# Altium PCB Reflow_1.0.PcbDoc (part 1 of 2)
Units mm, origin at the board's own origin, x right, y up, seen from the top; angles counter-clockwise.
Board outline 183 x 128.5 mm, 2 copper layers (Top Layer, Bottom Layer); 137 components, 94 nets, 418 pads, 91 vias.
Unrouted connection lines stored in the file: 2.
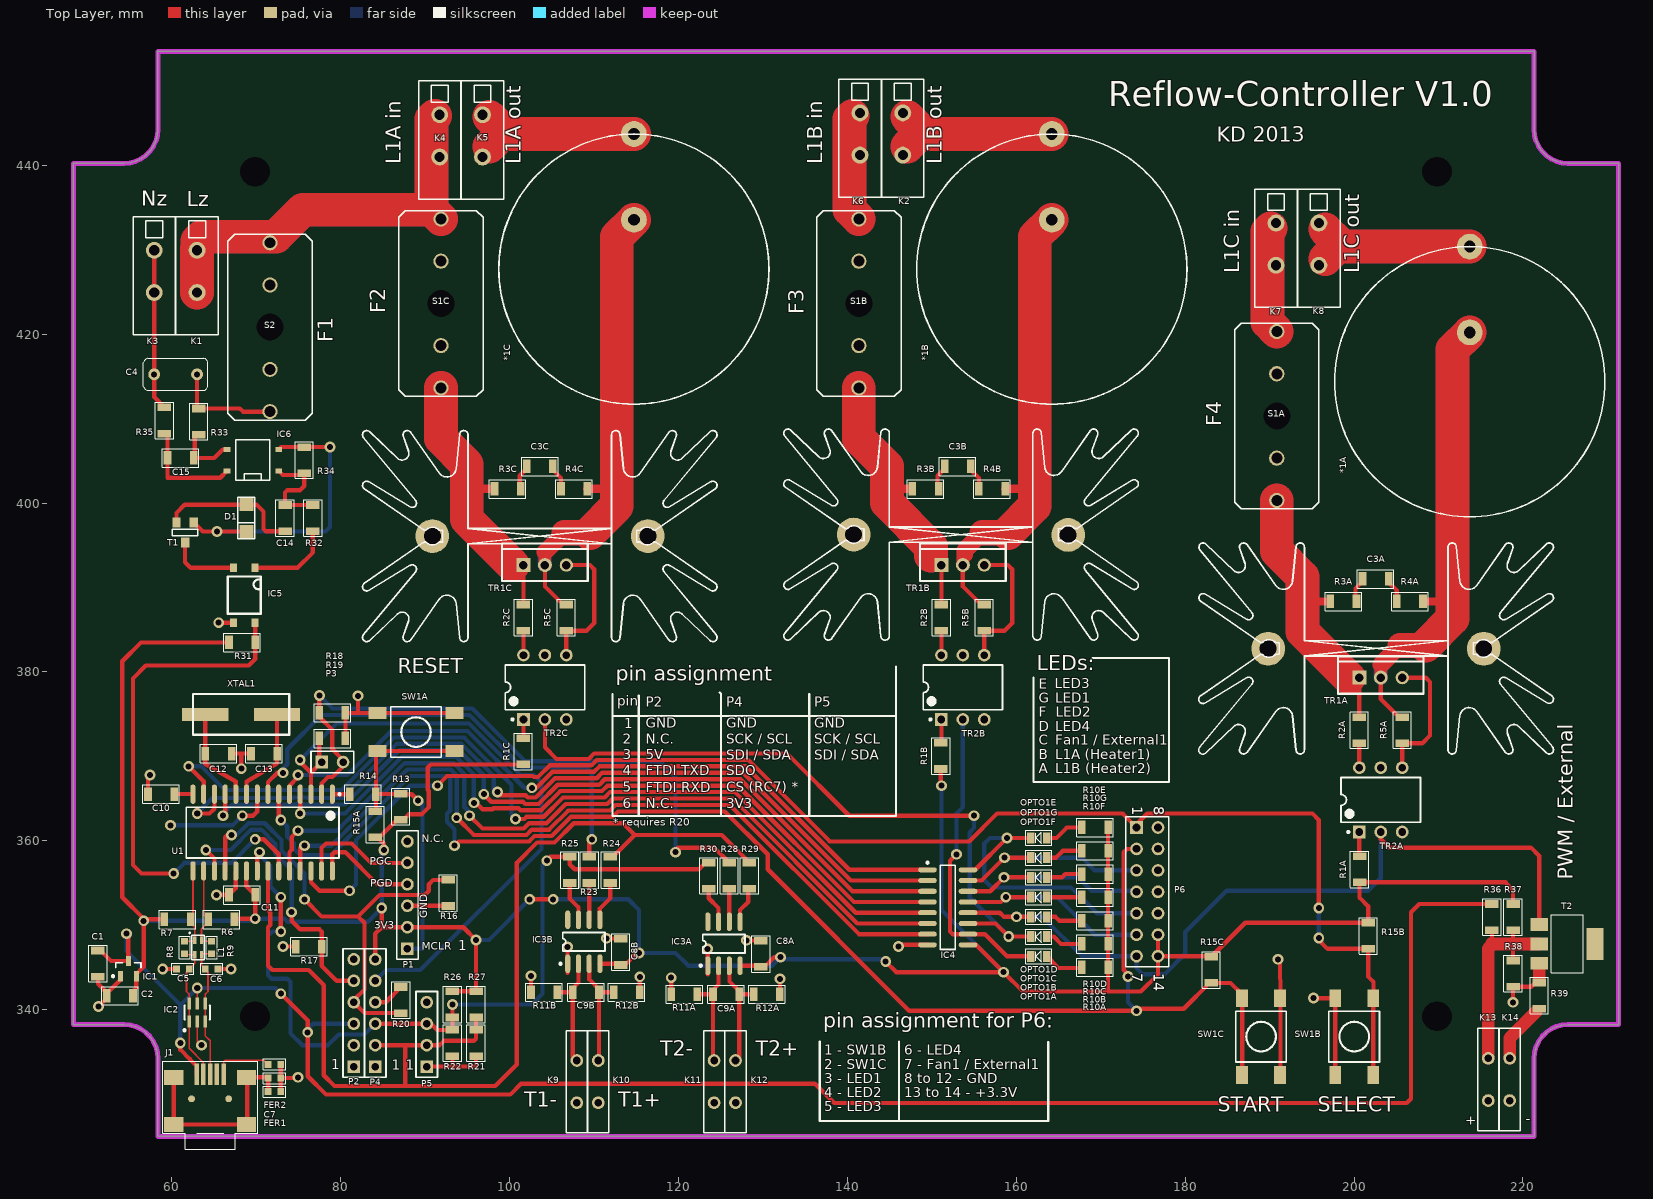
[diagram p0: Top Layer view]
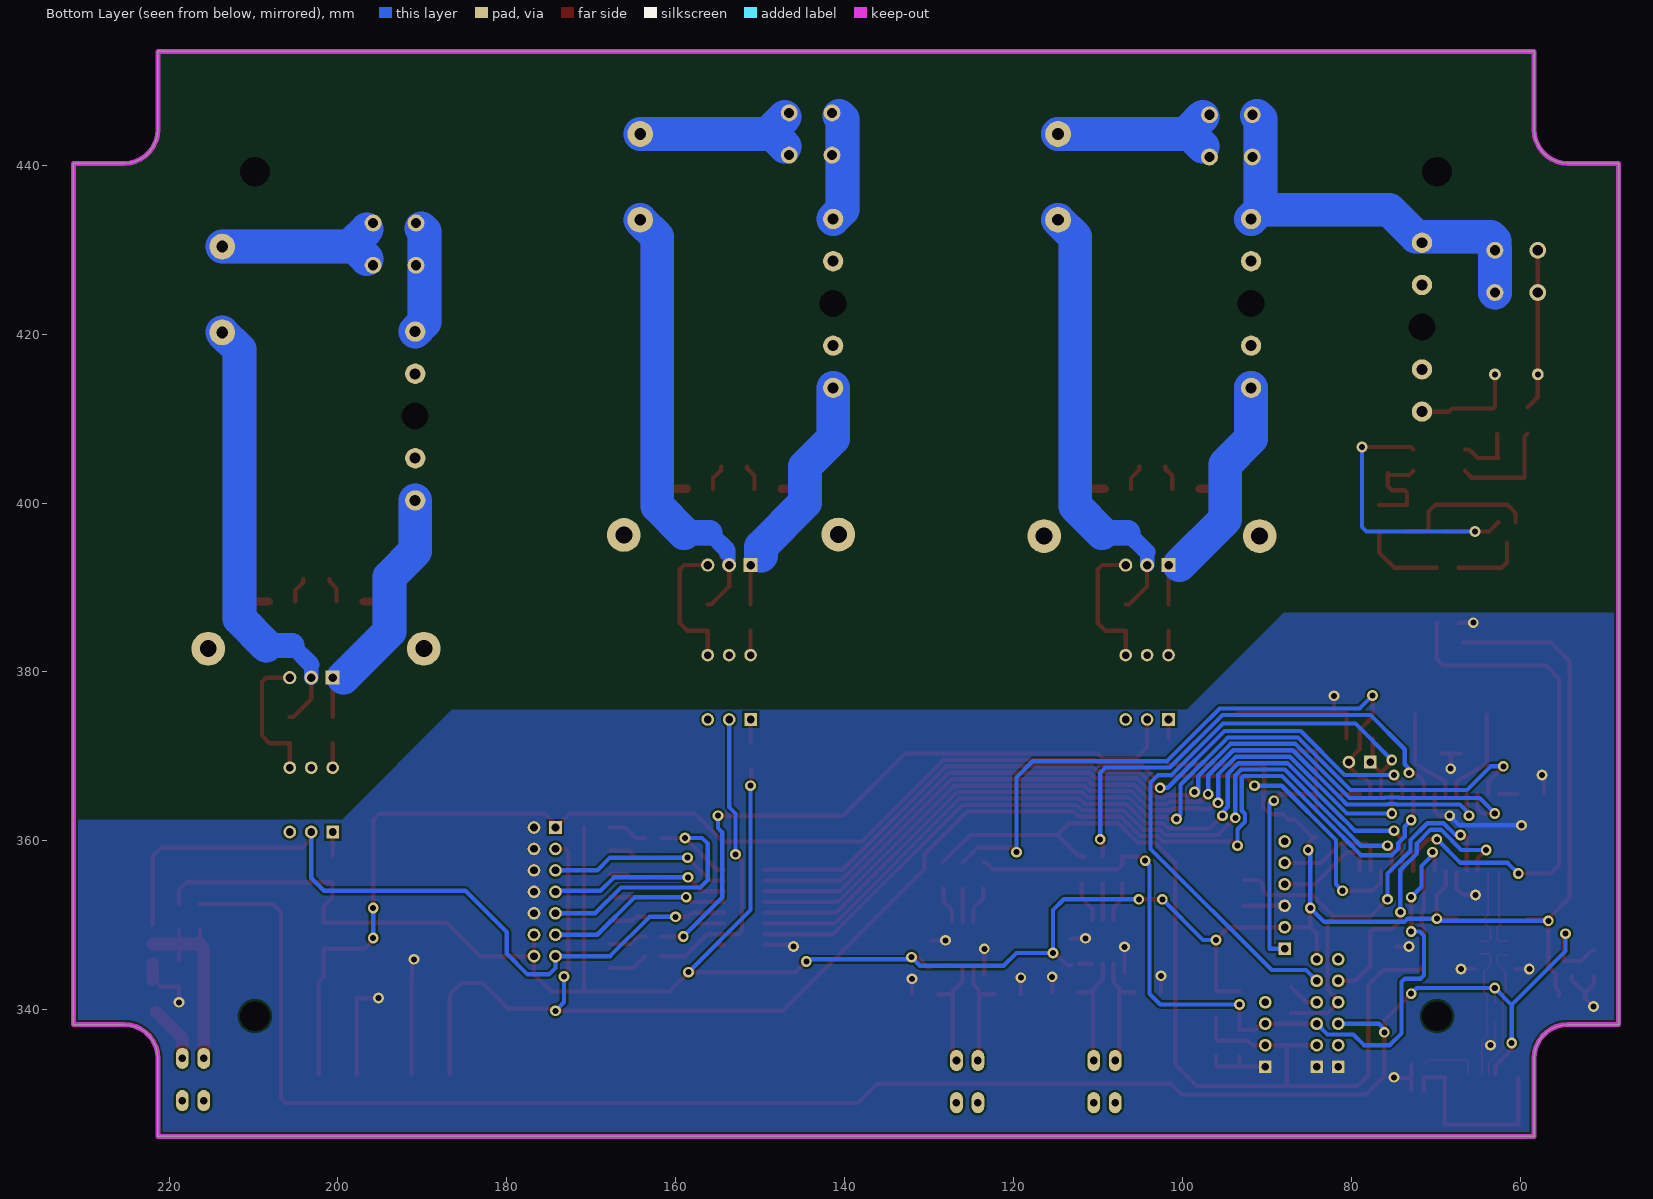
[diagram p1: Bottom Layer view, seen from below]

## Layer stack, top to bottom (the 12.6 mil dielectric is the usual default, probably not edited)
Top Layer: signal copper 0.0356
Dielectric: dielectric 0.32, FR-4, Dk 4.8
Bottom Layer: signal copper 0.0356

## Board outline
48.331,338.232 54.331,338.232 55.026,338.171 55.699,337.991 56.331,337.696 56.902,337.296 57.395,336.803 57.795,336.232 58.09,335.6 58.27,334.927 58.331,334.232 58.331,324.982 221.331,324.982 221.331,334.232 221.392,334.927 221.572,335.6 221.867,336.232 222.267,336.803 222.76,337.296 223.331,337.696 223.963,337.991 224.636,338.171 225.331,338.232 231.331,338.232 231.331,440.232 225.331,440.232 224.636,440.293 223.963,440.473 223.331,440.768 222.76,441.168 222.267,441.661 221.867,442.232 221.572,442.864 221.392,443.537 221.331,444.232 221.331,453.482 58.331,453.482 58.331,444.232 58.27,443.537 58.09,442.864 57.795,442.232 57.395,441.661 56.902,441.168 56.331,440.768 55.699,440.473 55.026,440.293 54.331,440.232 48.331,440.232

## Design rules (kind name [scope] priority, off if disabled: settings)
Clearance [All] p1: gap=0.254
ComponentClearance [All] p1 off: gap=0.254 collisioncheckmode=3 verticalgap=0.254 showdistances=FALSE
DiffPairsRouting [All] p1 off: maxlimit=0.254 minlimit=0.254 mostfreqgap=0.254 maxuncoupledlength=12.7
FabricationTestPointUsage [All] p1 off: valid=0 allowmultiple=FALSE
FabricationTestpoint [(IsPad And (OnTopLayer Or OnBottomLayer))] p1 off: side=3 testpointundercomponent=TRUE minsize=1.016 maxsize=2.54 preferedsize=1.524 minholesize=0 maxholesize=1.016 preferedholesize=0.813 testpointgrid=0.025 allowsidetop=TRUE allowsidebottom=TRUE usegrid=TRUE gridtolerance=0
FanoutControl Fanout_BGA [IsBGA] p1 off: bgadir=Out bgaviamode=Centered fanoutstyle=Auto fanoutdirection=Alternating viagrid=0.025 // Fanout_BGA (Default Rule)
FanoutControl Fanout_LCC [IsLCC] p2 off: bgadir=Out bgaviamode=Centered fanoutstyle=Auto fanoutdirection=Alternating viagrid=0.025 // Fanout_LCC (Default Rule)
FanoutControl Fanout_SOIC [IsSOIC] p3 off: bgadir=Out bgaviamode=Centered fanoutstyle=Auto fanoutdirection=Alternating viagrid=0.025 // Fanout_SOIC (Default Rule)
FanoutControl Fanout_Small [(CompPinCount < 5)] p4 off: bgadir=Out bgaviamode=Centered fanoutstyle=Auto fanoutdirection=OutThenIn viagrid=0.025 // Fanout_Small (Default Rule)
FanoutControl Fanout_Default [All] p5 off: bgadir=Out bgaviamode=Centered fanoutstyle=Auto fanoutdirection=Alternating viagrid=0.025 // Fanout_Default (Default Rule)
Height [All] p1 off: minheight=0 maxheight=25.4 prefheight=12.7
HoleSize [All] p1 off: absolutevalues=TRUE maxlimit=2.54 minlimit=0.025 maxpercent=80.000 minpercent=20.000
HoleToHoleClearance [All] p1 off: gap=0.254 allowstackedmicrovias=TRUE
LayerPairs [All] p1 off: enforce=TRUE
MinimumSolderMaskSliver [All] p1 off: minsoldermaskwidth=0.254
NetAntennae [All] p1 off: netantennaetolerance=0
PasteMaskExpansion [All] p1 off: expansion=0
PlaneClearance [All] p1 off: clearance=0.508
PlaneConnect [All] p1 off: planeconnectstyle=Relief reliefexpansion=0.508 reliefentries=4 reliefconductorwidth=0.254 reliefairgap=0.254
PolygonConnect [All] p1 off: connectstyle=Relief reliefconductorwidth=0.254 reliefentries=4 polygonreliefangle="90 Angle" airgapwidth=0.254
RoomDefinition U_SW3 [InComponentClass('U_SW3')] p1 off: confinementstyle=ConfineIn formatcopy=TRUE lockcomponents=FALSE outline 181.356,330.708 193.548,330.708 193.548,347.98 181.356,347.98
RoomDefinition U_SW2 [InComponentClass('U_SW2')] p2 off: confinementstyle=ConfineIn formatcopy=TRUE lockcomponents=FALSE outline 195.072,330.708 206.502,330.708 206.502,348.234 195.072,348.234
RoomDefinition U_SW1 [InComponentClass('U_SW1')] p3 off: confinementstyle=ConfineIn formatcopy=TRUE lockcomponents=FALSE outline 81.026,376.936 81.026,359.41 95.25,359.41 95.25,376.936
RoomDefinition U_AC_SWITCH3 [InComponentClass('U_AC_SWITCH3')] p4 off: confinementstyle=ConfineIn formatcopy=TRUE lockcomponents=FALSE outline 82.069,367.346 131.569,367.346 131.569,452.74 82.069,452.74
RoomDefinition U_AC_SWITCH2 [InComponentClass('U_AC_SWITCH2')] p5 off: confinementstyle=ConfineIn formatcopy=TRUE lockcomponents=FALSE outline 131.569,367.346 181.069,367.346 181.069,452.74 131.569,452.74
RoomDefinition U_ZEROCROSS [InComponentClass('U_ZEROCROSS')] p6 off: confinementstyle=ConfineIn formatcopy=TRUE lockcomponents=FALSE outline 81,380.694 81,436.786 52.813,436.786 52.813,380.694
RoomDefinition "U_USB ESD EMV BUCHSE" [InComponentClass('U_USB ESD EMV BUCHSE')] p7 off: confinementstyle=ConfineIn formatcopy=TRUE lockcomponents=FALSE outline 57.15,323.088 76.2,323.088 76.2,352.298 57.15,352.298
RoomDefinition U_UNL2003_LED [InComponentClass('U_UNL2003_LED')] p8 off: confinementstyle=ConfineIn formatcopy=TRUE lockcomponents=FALSE outline 146.4,325.628 178.816,325.628 178.816,364.744 146.4,364.744
RoomDefinition U_PIC18F2550 [InComponentClass('U_PIC18F2550')] p9 off: confinementstyle=ConfineIn formatcopy=TRUE lockcomponents=FALSE outline 56.134,378.968 56.134,344.678 96.273,344.678 96.273,378.968
RoomDefinition "U_MOSFET OUT" [InComponentClass('U_MOSFET OUT')] p10 off: confinementstyle=ConfineIn formatcopy=TRUE lockcomponents=FALSE outline 213.868,324.612 231.14,324.612 231.14,353.822 213.868,353.822
RoomDefinition U_MAX66752 [InComponentClass('U_MAX66752')] p11 off: confinementstyle=ConfineIn formatcopy=TRUE lockcomponents=FALSE outline 117.856,325.12 117.856,359.083 101.256,359.083 101.256,325.12
RoomDefinition U_MAX66751 [InComponentClass('U_MAX66751')] p12: confinementstyle=ConfineIn formatcopy=TRUE lockcomponents=FALSE outline 134.456,325.12 134.456,358.648 117.856,358.648 117.856,325.12
RoomDefinition U_AC_SWITCH1 [InComponentClass('U_AC_SWITCH1')] p13 off: confinementstyle=ConfineIn formatcopy=TRUE lockcomponents=FALSE outline 181.069,354.013 230.569,354.013 230.569,439.407 181.069,439.407
RoomDefinition U_3V3_Regler [InComponentClass('U_3V3_Regler')] p14 off: confinementstyle=ConfineIn formatcopy=TRUE lockcomponents=FALSE outline 48.26,338.074 57.53,338.074 57.53,349.504 48.26,349.504
RoutingCorners [All] p1 off: cornerstyle=45-Degree minsetback=2.54 maxsetback=2.54
RoutingLayers [All] p1 off: top layer_v5=TRUE bottom layer_v5=TRUE
RoutingPriority [All] p1 off: routingpriority=0
RoutingTopology [All] p1 off: topology=Shortest
RoutingVias [All] p1 off: holewidth=0.711 width=1.27 viastyle="Through Hole" minholewidth=0.711 minwidth=1.27 maxholewidth=0.711 maxwidth=1.27
ShortCircuit [All] p1 off: allowed=FALSE
SilkToSilkClearance [All] p1 off: silktosilkclearance=0.254
SilkscreenOverComponentPads [All] p1 off: minsilkscreentomaskgap=0.254
SolderMaskExpansion [All] p1 off: expansion=0.102
UnRoutedNet [All] p1 off:
Width [All] p1 off: maxlimit=0.254 minlimit=0.254 preferedwidth=0.254
2 further rules are at their usual default settings.

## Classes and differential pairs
channel class SW: U_SW1 U_SW2 U_SW3
channel class MAX6675: U_MAX66751 U_MAX66752
channel class LED: U_LED1 U_LED2 U_LED3 U_LED4 U_LED5 U_LED6 U_LED7
channel class AC_SWITCH: U_AC_SWITCH1 U_AC_SWITCH2 U_AC_SWITCH3
net class OUT[1..7]: OUT1 OUT2 OUT3 OUT4 OUT5 OUT6 OUT7
component class U_ZEROCROSS: C4 C14 C15 D1 IC5 IC6 R31 R32 R33 R34 R35 T1
component class "U_USB ESD EMV BUCHSE": C5 C6 C7 FER1 FER2 IC2 J1 L1 R6 R7 R8 R9
component class U_UNL2003_LED: IC4
component class U_SW3: R15C SW1C
component class U_SW2: R15B SW1B
component class U_SW1: R15A SW1A
component class U_PIC18F2550: C10 C11 C12 C13 P1 R13 R14 U1 XTAL1
component class "U_MOSFET OUT": K13 K14 R36 R37 R38 R39 T2
component class U_MAX66752: C8B C9B IC3B R11B R12B
component class U_MAX66751: C8A C9A IC3A R11A R12A
component class U_LED7: OPTO1G R10G
component class U_LED6: OPTO1F R10F
component class U_LED5: OPTO1E R10E
component class U_LED4: OPTO1D R10D
component class U_LED3: OPTO1C R10C
component class U_LED2: OPTO1B R10B
component class U_LED1: OPTO1A R10A
component class U_AC_SWITCH3: *1C C3C R1C R2C R3C R4C R5C S1C TR1C TR2C
component class U_AC_SWITCH2: *1B C3B R1B R2B R3B R4B R5B S1B TR1B TR2B
component class U_AC_SWITCH1: *1A C3A R1A R2A R3A R4A R5A S1A TR1A TR2A
component class U_3V3_Regler: C1 C2 IC1
component class TOP_Sheet: K1 K2 K3 K4 K5 K6 K7 K8 K9 K10 K11 K12 P2 P3 P4 P5 P6 R16 R17 R18 R19 R20 R21 R22 R23 R24 R25 R26 R27 R28 R29 R30 S2
differential pair USB: +USB_P -USB_N
differential pair USB1: +USB1_P -USB1_N

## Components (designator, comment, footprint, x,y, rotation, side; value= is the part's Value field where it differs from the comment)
*1A "Ringkern-Drossel_1mH_16A_250VAC" "PCBCOMPONENT_1 - DUPLICATE" 213.711,420.213 r90 top (schematic designator *1)
*1B "Ringkern-Drossel_1mH_16A_250VAC" "PCBCOMPONENT_1 - DUPLICATE" 164.211,433.546 r90 top (schematic designator *1)
*1C "Ringkern-Drossel_1mH_16A_250VAC" "PCBCOMPONENT_1 - DUPLICATE" 114.711,433.546 r90 top (schematic designator *1)
C1 "1uF" RLCDT_1206 51.23,345.452 r270 top
C2 "1uF" RLCDT_1206 53.83,341.652 r180 top
C3A "10nF" RLCDT_1206 202.561,391.003 r0 top (schematic designator C3)
C3B "10nF" RLCDT_1206 153.061,404.336 r0 top (schematic designator C3)
C3C "10nF" RLCDT_1206 103.561,404.336 r0 top (schematic designator C3)
C4 "VARISTOR_RM5" C02S200E0E28 62.973,415.238 r180 top
C5 "10pF" RLCDT_0603 61.292,344.816 r0 top
C6 "10pF" RLCDT_0603 64.692,344.816 r180 top
C7 "10nF" RLCDT_0603 72.136,331.895 r0 top
C8A "100nF" RLCDT_1206 129.756,346.601 r90 top (schematic designator C8)
C8B "100nF" RLCDT_1206 113.156,346.836 r90 top (schematic designator C8)
C9A "100nF" RLCDT_1206 125.63,341.83 r180 top (schematic designator C9)
C9B "100nF" RLCDT_1206 109.03,342.065 r180 top (schematic designator C9)
C10 "220nF" RLCDT_1206 58.706,365.528 r180 top
C11 "100nF" RLCDT_1206 68.298,353.586 r180 top
C12 "22pF" RLCDT_1206 65.506,370.328 r180 top
C13 "22pF" RLCDT_1206 70.906,370.328 r0 top
C14 "10uF" RLCDT_1206 73.387,398.22 r270 top
C15 "1nF" RLCDT_1206 61.016,405.332 r180 top
D1 "D_LL4148/MMELF" D02X125Y0A0 68.815,398.22 r90 top
FER1 "742792651" RLCDT_0603 72.136,330.295 r180 top
FER2 "742792651" RLCDT_0603 72.136,333.502 r0 top
IC1 "VRG_XC6206P332MR/SOT23" RLCDT_SOT23 54.83,344.852 r90 top
IC2 "IP4220CZ6" ESD_SOT457 62.992,339.654 r0 top
IC3A "IC_MAX6675" IC_SOIC150_8 125.376,347.799 r0 top (schematic designator IC3)
IC3B "IC_MAX6675" IC_SOIC150_8 108.776,348.034 r0 top (schematic designator IC3)
IC4 "ULN2003L" L16_N 151.88,352.11 r0 top
IC5 "OK_PC357/MFP4" MFP4 68.561,389.076 r180 top
IC6 "GLEICHRICHTER_S80" DO-269AA 69.577,405.078 r90 top
J1 "USB-MINI-B%C" USB-MINI-B_2 66.117,332.338 r180 top
K1 "WAGO-236" KL02X196Y0A0 62.973,427.43 r270 top
K2 "WAGO-236" KL02X196Y0A0 146.565,443.706 r270 top
K3 "WAGO-236" KL02X196Y0A0 57.893,427.43 r270 top
K4 "WAGO-236" KL02X196Y0A0 91.701,443.484 r270 top
K5 "WAGO-236" KL02X196Y0A0 96.781,443.484 r270 top
K6 "WAGO-236" KL02X196Y0A0 141.485,443.706 r270 top
K7 "WAGO-236" KL02X196Y0A0 190.761,430.659 r270 top
K8 "WAGO-236" KL02X196Y0A0 195.841,430.659 r270 top
K9 "WAGO-233" KL02X0Y197A0 107.95,331.47 r180 top
K10 "WAGO-233" KL02X0Y197A0 110.49,331.47 r180 top
K11 "WAGO-233" KL02X0Y197A0 124.206,331.47 r180 top
K12 "WAGO-233" KL02X0Y197A0 126.746,331.47 r180 top
K13 "WAGO-233" KL02X0Y197A0 215.9,331.724 r180 top
K14 "WAGO-233" KL02X0Y197A0 218.44,331.724 r180 top
L1 "744231371" RLCDT_CMC_WÜRTH_CNSW_0805 63.092,347.354 r270 top
OPTO1A "Value" OPTO_0805_POL 162.664,346.31 r180 top (schematic designator OPTO1)
OPTO1B "Value" OPTO_0805_POL 162.664,348.647 r180 top (schematic designator OPTO1)
OPTO1C "Value" OPTO_0805_POL 162.664,350.985 r180 top (schematic designator OPTO1)
OPTO1D "Value" OPTO_0805_POL 162.664,353.322 r180 top (schematic designator OPTO1)
OPTO1E "Value" OPTO_0805_POL 162.664,360.334 r180 top (schematic designator OPTO1)
OPTO1F "Value" OPTO_0805_POL 162.664,355.659 r180 top (schematic designator OPTO1)
OPTO1G "Value" OPTO_0805_POL 162.664,357.997 r180 top (schematic designator OPTO1)
P1 "Header 6" HDR1X6 87.884,347.218 r90 top
P2 "Header 6" HDR1X6 81.534,333.248 r90 top
P3 "Header 2" HDR1X2 77.724,369.316 r0 top
P4 "Header 6" HDR1X6 84.074,333.248 r90 top
P5 "Header 4" HDR1X4 90.17,333.248 r90 top
P6 "Header 7X2A" HDR2X7_CEN 174.244,361.569 r270 top
R1A "330R" RLCDT_1206 200.66,356.616 r90 top (schematic designator R1)
R1B "330R" RLCDT_1206 151.069,370.046 r90 top (schematic designator R1)
R1C "330R" RLCDT_1206 101.6,370.586 r90 top (schematic designator R1)
R2A "360R" RLCDT_1206 200.63,373.096 r270 top (schematic designator R2)
R2B "360R" RLCDT_1206 151.13,386.429 r270 top (schematic designator R2)
R2C "360R" RLCDT_1206 101.63,386.429 r270 top (schematic designator R2)
R3A "47R" RLCDT_1206 198.751,388.336 r0 top (schematic designator R3)
R3B "47R" RLCDT_1206 149.251,401.669 r0 top (schematic designator R3)
R3C "47R" RLCDT_1206 99.751,401.669 r0 top (schematic designator R3)
R4A "47R" RLCDT_1206 206.625,388.336 r0 top (schematic designator R4)
R4B "47R" RLCDT_1206 157.125,401.669 r0 top (schematic designator R4)
R4C "47R" RLCDT_1206 107.625,401.669 r0 top (schematic designator R4)
R5A "360R" RLCDT_1206 205.71,373.096 r90 top (schematic designator R5)
R5B "360R" RLCDT_1206 156.21,386.429 r90 top (schematic designator R5)
R5C "360R" RLCDT_1206 106.71,386.429 r90 top (schematic designator R5)
R6 "0R" RLCDT_1206 65.851,350.684 r180 top
R7 "0R" RLCDT_1206 60.651,350.684 r0 top
R8 "0R" RLCDT_0603 61.492,347.354 r90 top
R9 "0R" RLCDT_0603 64.692,347.354 r90 top
R10A "330R" RLCDT_1206 169.322,345.017 r0 top (schematic designator R10)
R10B "330R" RLCDT_1206 169.322,347.776 r0 top (schematic designator R10)
R10C "330R" RLCDT_1206 169.322,350.534 r0 top (schematic designator R10)
R10D "330R" RLCDT_1206 169.322,353.293 r0 top (schematic designator R10)
R10E "330R" RLCDT_1206 169.322,361.569 r0 top (schematic designator R10)
R10F "330R" RLCDT_1206 169.322,356.052 r0 top (schematic designator R10)
R10G "330R" RLCDT_1206 169.322,358.81 r0 top (schematic designator R10)
R11A "Varistor" RLCDT_1206 120.677,341.83 r0 top (schematic designator R11)
R11B "Varistor" RLCDT_1206 104.077,342.065 r0 top (schematic designator R11)
R12A "Varistor" RLCDT_1206 130.456,341.83 r180 top (schematic designator R12)
R12B "Varistor" RLCDT_1206 113.856,342.065 r180 top (schematic designator R12)
R13 "10K" RLCDT_1206 87.106,364.028 r270 top
R14 "470R" RLCDT_1206 82.606,365.528 r0 top
R15A "4K7" RLCDT_1206 84.074,361.95 r270 top (schematic designator R15)
R15B "4K7" RLCDT_1206 201.676,348.742 r90 top (schematic designator R15)
R15C "4K7" RLCDT_1206 183.092,344.71 r90 top (schematic designator R15)
R16 "Varistor" RLCDT_1206 92.71,353.822 r90 top
R17 "Varistor" RLCDT_1206 76.2,347.472 r0 top
R18 "Varistor" RLCDT_1206 78.994,375.158 r180 top
R19 "Varistor" RLCDT_1206 78.994,372.11 r180 top
R20 "33R" RLCDT_1206 87.122,341.122 r270 top
R21 "Varistor" RLCDT_1206 96.012,336.042 r90 top
R22 "Varistor" RLCDT_1206 93.218,336.042 r90 top
R23 "33R" RLCDT_1206 109.437,356.543 r270 top
R24 "33R" RLCDT_1206 111.925,356.543 r270 top
R25 "33R" RLCDT_1206 107.099,356.543 r270 top
R26 "4K7" RLCDT_1206 93.218,340.614 r90 top
R27 "4K7" RLCDT_1206 96.012,340.614 r90 top
R28 "33R" RLCDT_1206 126.011,355.854 r270 top
R29 "33R" RLCDT_1206 128.399,355.854 r270 top
R30 "33R" RLCDT_1206 123.573,355.854 r270 top
R31 "4K7" RLCDT_1206 68.307,383.488 r0 top
R32 "1K" RLCDT_1206 76.689,398.22 r90 top
R33 "220K" RLCDT_1206 63.175,409.65 r270 top
R34 "22K" RLCDT_1206 75.673,405.078 r270 top
R35 "220K" RLCDT_1206 59.111,409.777 r270 top
R36 "1K" RLCDT_1206 216.342,350.962 r270 top
R37 "1K" RLCDT_1206 218.842,350.962 r270 top
R38 "Varistor" RLCDT_1206 218.842,344.262 r90 top
R39 "100R" RLCDT_1206 221.942,341.662 r90 top
S1A "SICHERUNGSHALTER_MIRA" SICHERUNGSHALTER_MIRA 190.851,410.307 r270 top (schematic designator S1)
S1B "SICHERUNGSHALTER_MIRA" SICHERUNGSHALTER_MIRA 141.351,423.64 r270 top (schematic designator S1)
S1C "SICHERUNGSHALTER_MIRA" SICHERUNGSHALTER_MIRA 91.851,423.64 r270 top (schematic designator S1)
S2 "SICHERUNGSHALTER_MIRA" SICHERUNGSHALTER_MIRA 71.609,420.826 r270 top
SW1A "Aus Datenbank" MECH_TASTER_FSM6JSMA 88.9,372.872 r90 top (schematic designator SW1)
SW1B "Aus Datenbank" MECH_TASTER_FSM6JSMA 200.025,336.804 r180 top (schematic designator SW1)
SW1C "Aus Datenbank" MECH_TASTER_FSM6JSMA 188.992,336.804 r0 top (schematic designator SW1)
T1 "NT_BC847/SOT23" TR03X80Y95A0 62.566,397.712 r180 top
T2 "FN_PHT8N06LT/SOT223" SOT223 221.942,350.062 r90 top
TR1A "TRIAC_BTA140-800" TO-220 205.71,379.319 r0 top (schematic designator TR1)
TR1B "TRIAC_BTA140-800" TO-220 156.21,392.652 r0 top (schematic designator TR1)
TR1C "TRIAC_BTA140-800" TO-220 106.71,392.652 r0 top (schematic designator TR1)
TR2A "OPTOTRIAC_IS600x" DIP-6 203.17,364.841 r90 top (schematic designator TR2)
TR2B "OPTOTRIAC_IS600x" DIP-6 153.67,378.174 r90 top (schematic designator TR2)
TR2C "OPTOTRIAC_IS600x" DIP-6 104.17,378.174 r90 top (schematic designator TR2)
U1 "PIC18F2550-I/SO" SOIC-SO28_N 70.739,360.965 r270 top
XTAL1 "HCM49 4.000MABJ-UT" IC_M-HCM49 68.191,374.959 r180 top

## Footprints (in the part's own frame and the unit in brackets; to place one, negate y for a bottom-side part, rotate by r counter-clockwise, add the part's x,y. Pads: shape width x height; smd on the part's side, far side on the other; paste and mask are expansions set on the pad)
C02S200E0E28 [mil]
  round 55 hole 28: 1(0,0) 2(200,0)
  silkscreen extent -50,-75 250,75
D02X125Y0A0 [mil]
  rect 60x65 smd: A(62.5,0) K(-62.5,0)
  silkscreen extent -98,-40 98,40
DIP-6 [mm] "DIP; 6 Leads; Row Spacing 7.62 mm; Pitch 2.54 mm"
  rect 1.5x1.5 hole 0.9: 1(-3.81,2.54)
  round 1.5 hole 0.9: 2(-3.81,0) 3(-3.81,-2.54) 4(3.81,-2.54) 5(3.81,0) 6(3.81,2.54)
  silkscreen extent -3.93,-4.7 2.65,4.7, body extent -3.55,-4.7 3.55,4.7, height 5.46
DO-269AA [mm]
  rect 0.6x0.8 smd: 1(-1.27,-3.055) 2(1.27,-3.055) 3(1.27,3.055) 4(-1.27,3.055)
  silkscreen extent -2.4,-2 2.4,2
ESD_SOT457 [mm]
  rect 0.45x1.45 smd: 1(-0.95,-1.075) 2(0,-1.075) 3(0.95,-1.075) 4(0.95,1.075) 5(0,1.075) 6(-0.95,1.075)
  silkscreen extent -1.62,-2.22 1.5,0.85
HDR1X2 [mm] "Connector; Header; 2 Position"
  rect 1.5x1.5 hole 0.9: 1(0,0)
  round 1.5 hole 0.9: 2(2.54,0)
  silkscreen extent -1.27,-1.27 3.81,1.27
HDR1X4 [mm] "Connector; Header; 4 Position"
  rect 1.5x1.5 hole 0.9: 1(0,0)
  round 1.5 hole 0.9: 2(2.54,0) 3(5.08,0) 4(7.62,0)
  silkscreen extent -1.27,-1.27 8.89,1.27
HDR1X6 [mm] "Connector; Header; 6 Position"
  rect 1.5x1.5 hole 0.9: 1(0,0)
  round 1.5 hole 0.9: 2(2.54,0) 3(5.08,0) 4(7.62,0) 5(10.16,0) 6(12.7,0)
  silkscreen extent -1.27,-1.27 13.97,1.27
HDR2X7_CEN [mm] "Connector; Header; 7x2 Position"
  rect 1.5x1.5 hole 0.9: 1(0,0)
  round 1.5 hole 0.9: 2(2.54,0) 3(5.08,0) 4(7.62,0) 5(10.16,0) 6(12.7,0) 7(15.24,0) 8(0,2.54) 9(2.54,2.54) 10(5.08,2.54) 11(7.62,2.54) 12(10.16,2.54) 13(12.7,2.54) 14(15.24,2.54)
  silkscreen extent -1.27,-1.27 16.51,3.81
IC_M-HCM49 [mm] "Quarz 25MHz"
  rect 5.5x1.5 smd: 1(-4.25,0) 2(4.25,0)
  silkscreen extent -5.7,-2.4 5.7,2.4, body extent -5.7,-2.4 5.7,2.4, height 4.4
IC_SOIC150_8 [mm] "SOIC, 1.27mm, 150mil body"
  oval 0.6x2.2 smd: 1(-1.905,-2.6) 2(-0.635,-2.6) 3(0.635,-2.6) 4(1.905,-2.6) 5(1.905,2.6) 6(0.635,2.6) 7(-0.635,2.6) 8(-1.905,2.6)
  silkscreen extent -2.88,-2.72 2.5,1.1, body extent -2.67,-1.95 2.67,1.95, height 1.75
KL02X0Y197A0 [mm]
  round 1.5 / inner round 1.5 / far side oval 1.5x2.5 hole 0.9: 1(0,-2.5)
  round 1.5 / inner round 1.5 / far side oval 1.5x2.5 hole 0.889: 2(0,2.5)
  silkscreen extent -1.25,-6.05 1.25,6.05
KL02X196Y0A0 [mm]
  round 2 / inner round 1.6 / far side round 2 hole 1.2: 1(-2.5,0) 1(2.5,0)
  silkscreen extent -6.5,-2.5 7.5,2.5
L16_N [mm] "SOIC, 16-Leads, Body 9.9x3.9mm, Pitch 1.27mm, IPC Medium Density"
  oval 2.2x0.6 smd: 1(-2.4,4.445) 2(-2.4,3.175) 3(-2.4,1.905) 4(-2.4,0.635) 5(-2.4,-0.635) 6(-2.4,-1.905) 7(-2.4,-3.175) 8(-2.4,-4.445) 9(2.4,-4.445) 10(2.4,-3.175) 11(2.4,-1.905) 12(2.4,-0.635) 13(2.4,0.635) 14(2.4,1.905) 15(2.4,3.175) 16(2.4,4.445)
  silkscreen extent -2.52,-5 0.9,5.42, body extent -1.95,-4.95 1.95,4.95, height 1.75
MECH_TASTER_FSM6JSMA [mm] "6x6mm"
  rect 1.4x2.1 smd: 1(-2.25,4.55) 2(-2.25,-4.55) 3(2.25,4.55) 4(2.25,-4.55)
  silkscreen extent -3,-3 3,3, body extent -3,-3 3,3, height 3.57
MFP4 [mm]
  rect 0.8x1 smd: A(-1.27,-3.25) E(1.27,3.25) KA(1.27,-3.25) KO(-1.27,3.25)
  silkscreen extent -1.95,-2.2 1.95,2.2
OPTO_0805_POL [mm] "Chip Resistor; Body 2.0 x 1.3 mm (LxW typ)"
  rect 0.9x1.3 smd: A(-0.95,0) K(0.95,0)
  silkscreen extent -1.56,-0.88 1.56,0.88, body extent -1,-0.65 1,0.65, height 1.35
"PCBCOMPONENT_1 - DUPLICATE" [mil]
  round 120 hole 55: 0(0,0) 1(400,0)
  silkscreen extent -860,-630 400,630
RLCDT_0603 [mm] "Chip Resistor; Body 1.6 x 0.8 mm (LxW typ)"
  rect 0.8x0.8 smd: 1(-0.75,0) 2(0.75,0)
  silkscreen extent -1.31,-0.65 1.31,0.65, body extent -0.8,-0.45 0.8,0.45, height 1.25
RLCDT_1206 [mm] "Chip Resistor; Body 3.2 x 1.6 mm (LxW typ)"
  rect 0.9x1.6 smd: 1(-1.55,0) 2(1.55,0)
  silkscreen extent -2.16,-1.08 2.16,1.08, body extent -1.6,-0.8 1.6,0.8, height 1.25
RLCDT_CMC_WÜRTH_CNSW_0805 [mm]
  rect 0.9x0.4 smd: 1(-0.85,-0.4) 2(0.85,-0.4) 3(0.85,0.4) 4(-0.85,0.4)
  silkscreen extent -1.8,-1.07 1.45,0.75, body extent -1.1,-0.7 1.1,0.7, height 1.4
RLCDT_SOT23 [mm] "SOT23 Gehäuse"
  rect 1.2x0.6 smd: 1(-0.9,0.95) 2(-0.9,-0.95) 3(0.9,0)
  silkscreen extent -1.02,-1.5 0.7,1.92, body extent -0.7,-1.5 0.7,1.5, height 1.1
SICHERUNGSHALTER_MIRA [mm]
  round 1.8 / inner round 1.8 / far side round 2.4 hole 1.3: 1(-10,0) 2(-5,0) 3(5,0) 4(10,0)
  round 0 hole 3.2: 5(0,0)
  silkscreen extent -11,-5 11,5
SOIC-SO28_N [mm] "SOIC, 28-Leads, Body 17.9x7.5mm, Pitch 1.27mm, IPC Medium Density"
  oval 2.3x0.6 smd: 1(-4.55,8.255) 2(-4.55,6.985) 3(-4.55,5.715) 4(-4.55,4.445) 5(-4.55,3.175) 6(-4.55,1.905) 7(-4.55,0.635) 8(-4.55,-0.635) 9(-4.55,-1.905) 10(-4.55,-3.175) 11(-4.55,-4.445) 12(-4.55,-5.715) 13(-4.55,-6.985) 14(-4.55,-8.255) 15(4.55,-8.255) 16(4.55,-6.985) 17(4.55,-5.715) 18(4.55,-4.445) 19(4.55,-3.175) 20(4.55,-1.905) 21(4.55,-0.635) 22(4.55,0.635) 23(4.55,1.905) 24(4.55,3.175) 25(4.55,4.445) 26(4.55,5.715) 27(4.55,6.985) 28(4.55,8.255)
  silkscreen extent -4.67,-9.05 3,9.23, body extent -3.8,-9.06 3.8,9.06, height 2.65
SOT223 [mil]
  rect 60x80 smd: 1(0,0) 2(-90,0) 3(-180,0)
  rect 150x80 smd: 4(-90,-260)
  silkscreen extent -225,-205 45,-55
TO-220 [mil]
  rect 65x65 hole 39.4: 1(-200,0)
  round 65 hole 39.4: 2(-100,0)
  round 62 hole 39.4: 3(0,0)
  silkscreen extent -300,-75 100,100
TR03X80Y95A0 [mil]
  rect 39x47 smd: B(0,0) C(40,95) E(80,0)
  silkscreen extent -20,31 100,63
USB-MINI-B_2 [mil]
  rect 20x100 smd: 1(0,0) 2(31.5,0) 3(62.99,0) 4(94.49,0) 5(125.98,0)
  rect 90x70 smd: 6(-106.99,234.17) 7(-106.99,14.17) 8(233.01,14.17) 9(233.01,234.17)
  round 32 smd: ""(-23.62,114.17) ""(149.61,114.17)
  silkscreen extent -160,-60 285,350

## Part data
C1 C2 C3A C3B C3C C5 C6 C7 C8A C8B C9A C9B C10 C11 C12 C13 C14 C15: library part C_KERAMIK, "Kondensator, Keramik"
FER1 FER2: library part FER, "Ferrit"
IC1: "VOLTAGE REGULATOR 3V3 250mA"
IC2: library part ESD_IP4220CZ6, "ESD, USB, level4, 8kV"
IC4: "High-Voltage, High-Current Darlington Array"
K1 K2 K3 K4 K5 K6 K7 K8: "CAGE CLAMP RM5 WAGO236 SERIES"
K9 K10 K11 K12 K13 K14: "CAGE CLAMP RM2.5"
L1: library part L_CMC, "Common Mode Choke, Spule"
OPTO1A OPTO1B OPTO1C OPTO1D OPTO1E OPTO1F OPTO1G: library part OPTO_LED_KP-2012MGC, "LED, 0805, mega green"
P1 P2 P4: "Header, 6-Pin"
P3: "Header, 2-Pin"
P5: "Header, 4-Pin"
P6: "Header, 7-Pin, Dual row"
R1A R1B R1C R2A R2B R2C R3A R3B R3C R4A R4B R4C R5A R5B R5C R6 R7 R8 R9 R10A R10B R10C R10D R10E R10F R10G R11A R11B R12A R12B R13 R14 R15A R15B R15C R16 R17 R18 R19 R20 R21 R22 R23 R24 R25 R26 R27 R28 R29 R30 R31 R32 R33 R34 R35 R36 R37 R38 R39: library part R, "Widerstand"
SW1A SW1B SW1C: library part MECH_TASTER_FSM6JSMA, "SPNO, SMD, 6x6mm, H=3,57mm"
T2: "DIGITAL N-CHAN POWER MOSFET 25V 0R6 0A95"
U1: "High Performance, Enhanced Flash, USB Microcontroller with nanoWatt Technology, 32K Flash, 28-Pin SOIC, Industrial Temperature Range"
XTAL1: library part IC_XTAL_4MHz, "Quarz 4MHz"

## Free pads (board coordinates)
  round 4 hole 2: 0(90.835,396.081) 0(140.741,396.265) 0(189.835,382.748) 1(116.362,396.081) 1(166.141,396.215) 1(215.362,382.748)
  round 0 hole 3.5: 1(69.831,339.232) 1(69.831,439.232) 1(209.831,339.232) 1(209.831,439.232)

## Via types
v1: diameter 1.27, hole 0.711, Top Layer to Bottom Layer, 91 vias

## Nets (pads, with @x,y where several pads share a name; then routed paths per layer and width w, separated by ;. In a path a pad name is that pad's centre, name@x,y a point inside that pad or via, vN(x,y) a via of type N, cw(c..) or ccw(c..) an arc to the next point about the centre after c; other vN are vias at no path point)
3V3: C2.1 C8A.1 C8B.1 C11.1 IC1.2 IC3A.4 IC3B.4 IC4.9 P1.2 P4.6 P6.13 P6.14 R1A.1 R1B.1 R1C.1 R6.1 R7.1 R10A.2 R10B.2 R10C.2 R10D.2 R10E.2 R10F.2 R10G.2 R13.2 R15A.2 R15B.2 R15C.2 R26.2 R27.2 R31.1 R37.1 U1.20 | length 363.7
  Top Layer w0.508: C2.1@55.38,341.652 55.38,342.202 55.78,342.602 IC1.2@55.78,343.952 ; IC1.2@55.805,344.231 56.642,345.068 v1(56.642,350.52) ; R7.1@59.101,350.684 56.806,350.684 v1(56.642,350.52) ; R31.1@66.757,383.488 56.336,383.488 54.102,381.254 54.102,353.314 56.642,350.774 v1(56.642,350.52) ; R6.1@67.401,350.684 67.491,350.774 v1(69.85,350.774) 69.848,350.776 C11.1@69.848,353.586 ; U1.20@68.806,356.415 68.806,354.628 C11.1@69.796,353.638 ; P4.6@84.074,345.948 84.074,348.996 84.836,349.758 ; R15A.2@84.074,360.4 84.354,360.4 85.09,359.664 v1@85.09,359.156 ; R15A.2@84.556,360.4 86.634,362.478 R13.2@87.106,362.478 ; v1(84.836,352.044) 84.836,349.758 ; R13.2@87.376,362.458 88.043,363.125 89.567,363.125 90.424,363.982 90.424,365.922 90.297,366.049 90.297,368.681 90.652,369.036 R1C.1@101.6,369.036 ; R26.2@93.218,342.164 R27.2@96.012,342.164 v1(96.012,348.234) 94.488,349.758 P1.2@87.884,349.758 84.836,349.758 ; v1(102.362,353.06) v1(105.156,353.06) v1@105.41,353.06 ; IC3B.4@110.681,345.434 112.272,345.434 ; C8B.1@113.156,345.286 113.638,345.286 115.062,346.71 v1(115.316,346.71) ; IC3A.4@127.281,345.199 128.872,345.199 ; C8A.1@129.756,345.051 130.167,345.051 131.318,346.202 v1(132.08,346.202) ; v1(144.526,345.694) 145.795,344.425 v1(158.495,344.425) ; R1B.1@151.069,368.496 151.069,366.583 v1(151.13,366.522) ; IC4.9@154.28,347.665 155.255,347.665 v1(158.495,344.425) ; R10E.2@170.872,361.569 R10G.2@170.872,358.81 R10F.2@170.872,356.052 R10D.2@170.872,353.293 R10C.2@170.872,350.534 R10B.2@170.872,347.776 R10A.2@170.872,345.017 170.872,342.208 170.942,342.138 ; P6.13@176.784,348.869 P6.14@176.784,346.329 ; R37.1@218.842,352.912 R37.1@218.842,352.512 218.842,354.182 217.958,355.066 R1A.1@200.66,355.066 200.66,353.262 201.676,352.246 R15B.2@201.676,350.292 187.124,350.292 R15C.2@183.092,346.26 183.023,346.329 P6.14@176.784,346.329 ; v1(158.495,344.425) 160.782,342.138 170.942,342.138 ; 170.942,342.138 174.752,342.138 176.784,344.17 P6.14@176.784,346.329
  Bottom Layer w0.508: v1(56.642,350.52) 69.596,350.52 v1(69.85,350.774) 73.314,350.774 73.695,350.393 83.185,350.393 v1(84.836,352.044) 84.836,358.648 v1(85.09,358.902) ; v1(96.012,348.234) 97.536,348.234 v1(102.362,353.06) ; v1@105.41,353.06 114.046,353.06 115.316,351.79 v1(115.316,346.71) 119.634,346.71 121.158,345.186 131.064,345.186 v1(132.08,346.202) 132.334,345.948 144.272,345.948 v1(144.526,345.694) ; v1(151.13,366.522) 151.13,351.79 v1(158.495,344.425)
\SYNC: IC5.KO R31.2 U1.23 | length 64.2
  Top Layer w0.508: v1(60.198,356.108) 56.388,356.108 55.372,357.124 55.372,379.222 56.896,380.746 69.088,380.746 69.857,381.515 R31.2@69.857,383.488 69.857,385.8 IC5.KO@69.831,385.826 ; v1(69.85,360.172) 70.866,360.172 72.644,358.394 U1.23@72.644,356.415
  Bottom Layer w0.508: v1(60.198,356.108) 61.468,357.378 67.056,357.378 v1(69.85,360.172) v1@70.111,360.172
CS2: P3.2 R18.2 R28.1 U1.2 | length 76.3
  Top Layer w0.508: v1(77.47,377.19) 77.444,377.164 R18.2@77.444,375.158 77.444,374.676 78.994,373.126 78.994,370.84 80.264,369.57 P3.2@80.264,369.316 80.264,368.808 78.994,367.538 78.486,367.538 77.724,366.776 U1.2@77.724,365.515 ; v1@119.634,358.902 119.888,359.156 124.259,359.156 R28.1@126.011,357.404
  Bottom Layer w0.508: v1(77.47,377.19) 78.994,375.666 94.742,375.666 ; 94.934,375.666 95.566,375.666 98.126,373.106 101.806,369.426 117.712,369.426 119.634,367.503 v1(119.634,358.648)
CS3: P3.1 P4.5 R19.2 U1.3 | length 76.6
  Top Layer w0.508: v1(75.184,369.57) 75.184,369.316 76.454,368.046 ; U1.3@76.454,365.515 76.454,368.046 ; R19.2@77.444,372.11 77.444,369.596 P3.1@77.724,369.316 76.454,368.046
  Bottom Layer w0.508: v1(75.184,369.57) 79.502,373.888 95.188,373.888 101.284,367.792 102.87,367.792 103.759,366.903 103.759,359.029 89.408,344.678 85.344,344.678 P4.5@84.074,343.408
FTDI_RXD: P2.5 R17.2 U1.17 | length 35.5
  Top Layer w0.508: v1(64.008,358.902) 65.024,357.886 U1.17@65.024,356.415 ; v1(74.168,351.536) 74.168,350.52 75.184,349.504 77.47,349.504 77.75,349.224 R17.2@77.75,347.472 77.75,347.192 77.724,347.218 77.724,345.186 79.502,343.408 P2.5@81.534,343.408
  Bottom Layer w0.508: v1(64.008,358.902) 66.956,358.902 69.369,361.315 70.585,361.315 72.217,359.683 72.217,358.506 74.168,356.554 v1(74.168,351.536)
FTDI_TXD: P2.4 R16.2 R20.2 U1.18 | length 57.6
  Top Layer w0.508: U1.18@66.294,356.415 66.294,360.426 66.548,360.68 v1(67.056,360.68) ; v1(75.692,353.06) 77.724,351.028 82.042,351.028 ; R20.2@87.122,339.572 87.108,339.586 82.816,339.586 P2.4@81.534,340.868 81.534,341.122 82.792,342.38 82.792,350.278 82.042,351.028 ; R16.2@92.71,355.372 92.684,355.346 90.932,355.346 90.424,354.838 90.424,354.076 89.928,353.58 84.594,353.58 82.042,351.028
  Bottom Layer w0.508: v1(67.056,360.68) 67.656,360.68 69.053,362.077 70.993,362.077 72.979,360.091 72.979,358.821 75.692,356.108 v1(75.692,353.06)
GND: C1.2 C2.2 C5.1 C6.1 C7.2 C8A.2 C8B.2 C10.2 C11.2 C12.1 C13.1 FER1.1 FER2.2 IC1.1 IC2.2 IC3A.1 IC3B.1 IC4.8 IC5.E P1.3 P2.1 P4.1 P5.1 P6.8 P6.9 P6.10 P6.11 P6.12 R11A.1 R11B.1 R12A.1 R12B.1 R16.1 R17.1 R18.1 R19.1 R21.1 R22.1 R38.1 R39.2 SW1A.3 SW1A.4 SW1B.3 SW1B.4 SW1C.3 SW1C.4 T2.3 U1.8 U1.19 | length 130.3
  Top Layer w0.2: IC2.2@62.992,338.579 62.992,336.154 v1@63.358,335.788
  Top Layer w0.508: C1.2@51.23,343.902 51.23,343.052 52.28,342.002 C2.2@52.28,341.652 ; v1(51.308,340.36) 52.28,341.332 C2.2@52.28,341.652 ; IC1.1@53.88,343.952 53.88,343.502 52.28,341.902 C2.2@52.28,341.652 ; C10.2@57.156,365.528 v1@57.156,367.544 ; v1(58.892,344.816) C5.1@60.542,344.816 ; v1(65.278,353.568) 65.296,353.586 C11.2@66.748,353.586 67.536,354.374 U1.19@67.536,356.228 ; C6.1@65.442,344.816 v1(66.992,344.816) ; v1(65.532,385.826) IC5.E@67.291,385.826 ; C12.1@67.056,370.328 68.206,370.328 ; v1(68.206,368.528) 68.206,370.328 ; v1(68.326,362.966) 69.596,362.966 70.104,363.474 U1.8@70.104,365.515 ; C13.1@69.356,370.328 68.206,370.328 ; C7.2@72.886,331.895 C7.2@72.898,331.895 ; FER1.1@72.898,330.465 C7.2@72.898,331.895 ; FER2.2@72.898,333.502 C7.2@72.898,331.895 ; v1(73.152,347.472) R17.1@74.65,347.472 ; v1@74.847,331.895 C7.2@72.898,331.895 ; R19.1@80.544,372.11 R18.1@80.544,375.158 80.58,375.122 82.042,375.122 ; v1(82.042,377.165) 82.042,375.122 ; P1.3@87.884,352.298 92.684,352.298 R16.1@92.71,352.272 ; P5.1@90.17,333.248 93.218,333.248 ; R22.1@93.218,334.492 93.218,333.248 ; SW1A.4@93.45,375.122 SW1A.3@84.35,375.122 82.042,375.122 ; R21.1@96.012,334.492 96.012,333.248 93.218,333.248 ; R11B.1@102.527,342.065 v1(102.527,344.007) ; IC3B.1@106.856,344.346 v1(106.856,347.436) ; v1(111.456,348.436) 111.556,348.436 C8B.2@113.156,348.386 ; R12B.1@115.406,342.065 v1(115.406,343.886) v1@115.418,343.898 ; R11A.1@119.127,341.83 v1(119.127,343.772) ; IC3A.1@123.456,344.182 v1(123.456,347.201) ; v1(128.056,348.201) 128.156,348.201 C8A.2@129.756,348.151 ; R12A.1@132.006,341.83 v1(132.006,343.651) ; v1(146.05,347.472) 146.243,347.665 IC4.8@149.48,347.665 ; v1(191.008,345.948) 191.242,345.714 191.293,341.411 SW1C.4@191.293,332.311 ; v1(195.199,341.376) 195.221,341.354 SW1B.4@197.775,341.354 SW1B.3@197.775,332.254 ; v1(218.842,340.868) R38.1@218.842,342.712 220.992,342.712 221.492,343.212 R39.2@221.942,343.212
  Top Layer w1.5: R39.2@221.942,343.562 T2.3@221.942,345.49
  Bottom Layer w0.508: v1(59.817,361.823) 67.183,361.823 v1(68.326,362.966) ; v1@74.676,331.978 v1(74.93,331.978) ; v1@102.436,343.916 v1(102.527,344.007) ; v1@131.741,343.916 v1(132.006,343.651)
  other v1: 63.5,335.788 57.404,367.792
